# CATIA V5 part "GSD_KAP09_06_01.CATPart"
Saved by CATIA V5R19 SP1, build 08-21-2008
Part number: GSD_REPETITION_05
Description: Beispielmodell: Benutzermuster  Maik Hertha IT Consultants
Bounding box of the stored display mesh (mm): x -133.57 to 84.189, y -131.021 to 119.166, z 20 to 20
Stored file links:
  \GSD_LOFT\GSD_REPETITION_05.CATPart
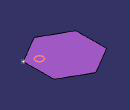
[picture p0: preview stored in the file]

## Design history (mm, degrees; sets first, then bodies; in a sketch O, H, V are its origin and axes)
AxisSystem1: origin (0, 0, 0), X (1, 0, 0), Y (0, 1, 0), Z (0, 0, 1)
Set1
  Plane1: type Equation, A 0, B 0, C 1, RefAxis AxisSystem1, Length 20
  Sketch1 on Plane1, origin (0, 0, 20), H (1, 0, 0), V (0, 1, 0)
    point P1 (-24.6903, -5.9273)
    point P2 (-23.5993, -131.0208)
    point P3 (84.1894, -67.5291)
    point P4 (83.0983, 57.5644)
    point P5 (-25.7814, 119.1662)
    point P6 (-133.57, 55.6746)
    point P7 (-132.4789, -69.4189)
    point P8 (30.295, -99.275)
    line L1 (-23.5993, -131.0208) -> (84.1894, -67.5291)
    line L2 (84.1894, -67.5291) -> (83.0983, 57.5644)
    line L3 (83.0983, 57.5644) -> (-25.7814, 119.1662)
    line L4 (-25.7814, 119.1662) -> (-133.57, 55.6746)
    line L5 (-133.57, 55.6746) -> (-132.4789, -69.4189)
    line L6 (-132.4789, -69.4189) -> (-23.5993, -131.0208)
    construction line L7 (-24.6903, -5.9273) -> (30.295, -99.275)
    construction circle A1 centre (-24.6903, -5.9273) radius 125.0983
    construction arc A2 centre (-133.57, 55.6746) radius 125.0983 from (-25.7814, 119.1662) to (-132.4789, -69.4189) cw
    construction arc A3 centre (84.1894, -67.5291) radius 125.0983 from (83.0983, 57.5644) to (-23.5993, -131.0208) ccw
    coincidence: A1 P2, A1 P3, A1 P4, A1 P5, A1 P6, A1 P7, A2 P1, A3 P1
    midpoint: P8 L1
    parallelism: L1 L4
  Split1: ToCut Plane1, Cutting Sketch1
  Extremum1: Reference Split1, Direction2 (0, 1, 0), Direction3 (0, 0, 1), Direction (1, 0, 0)
  Point1: type OnPlane, Support Split1, Direction (1, 0, 0), H -43.408, V 22.195, RefPoint Extremum1
  Sketch2 on Plane1, origin (40.7814, -45.3341, 20), H (-1, 0, 0), V (0, -1, 0)
    circle A1 centre (0, 0) radius 15
    curve C1
    radius A1 = 15
Set2
  Sketch3 on Plane1, origin (0, 0, 20), H (1, 0, 0), V (0, 1, 0)
    point P1 (-92.9234, 45.0039)
    point P2 (49.346, 41.4456)
    point P3 (36.4418, 0.3629)
    point P4 (-92.9234, -44.925)
    point P5 (-23.563, -44.925)
    point P6 (-23.563, 80.2638)
    point P7 (-23.563, -99.5941)
    point P8 (-23.563, 28.5062)
  DatumPoint1 "Versatzpunkt.1": linked copy from another document
Body1 (main body)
